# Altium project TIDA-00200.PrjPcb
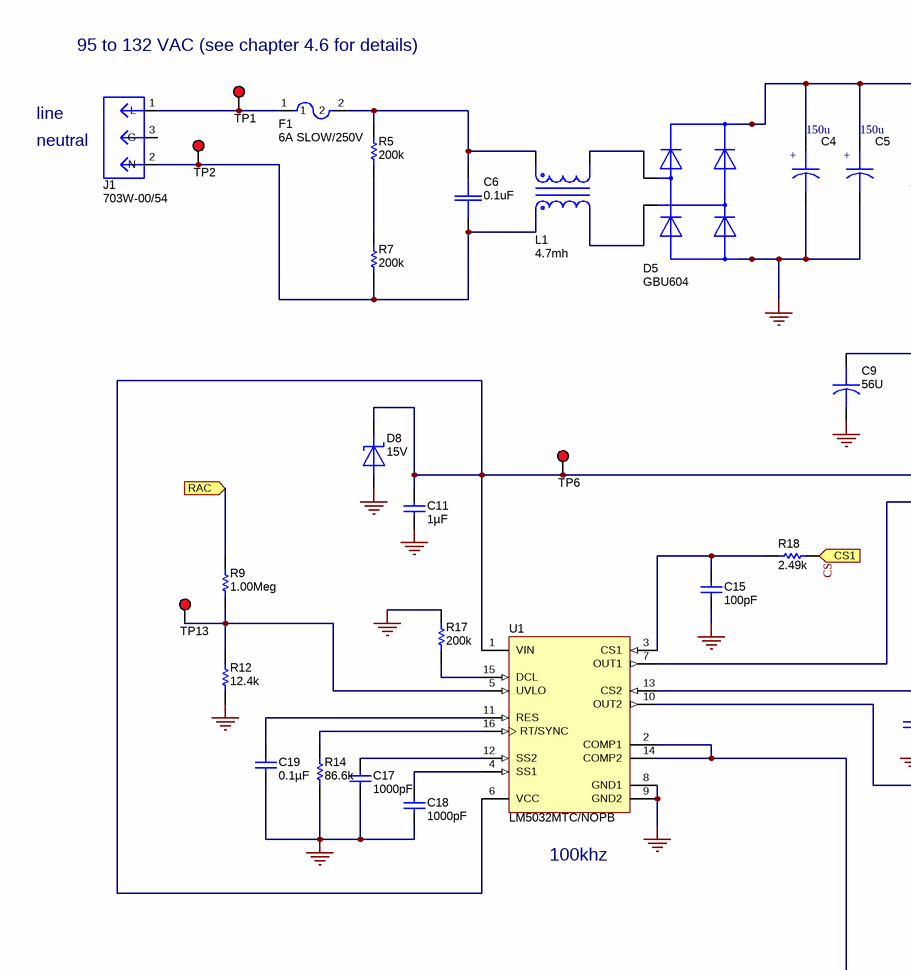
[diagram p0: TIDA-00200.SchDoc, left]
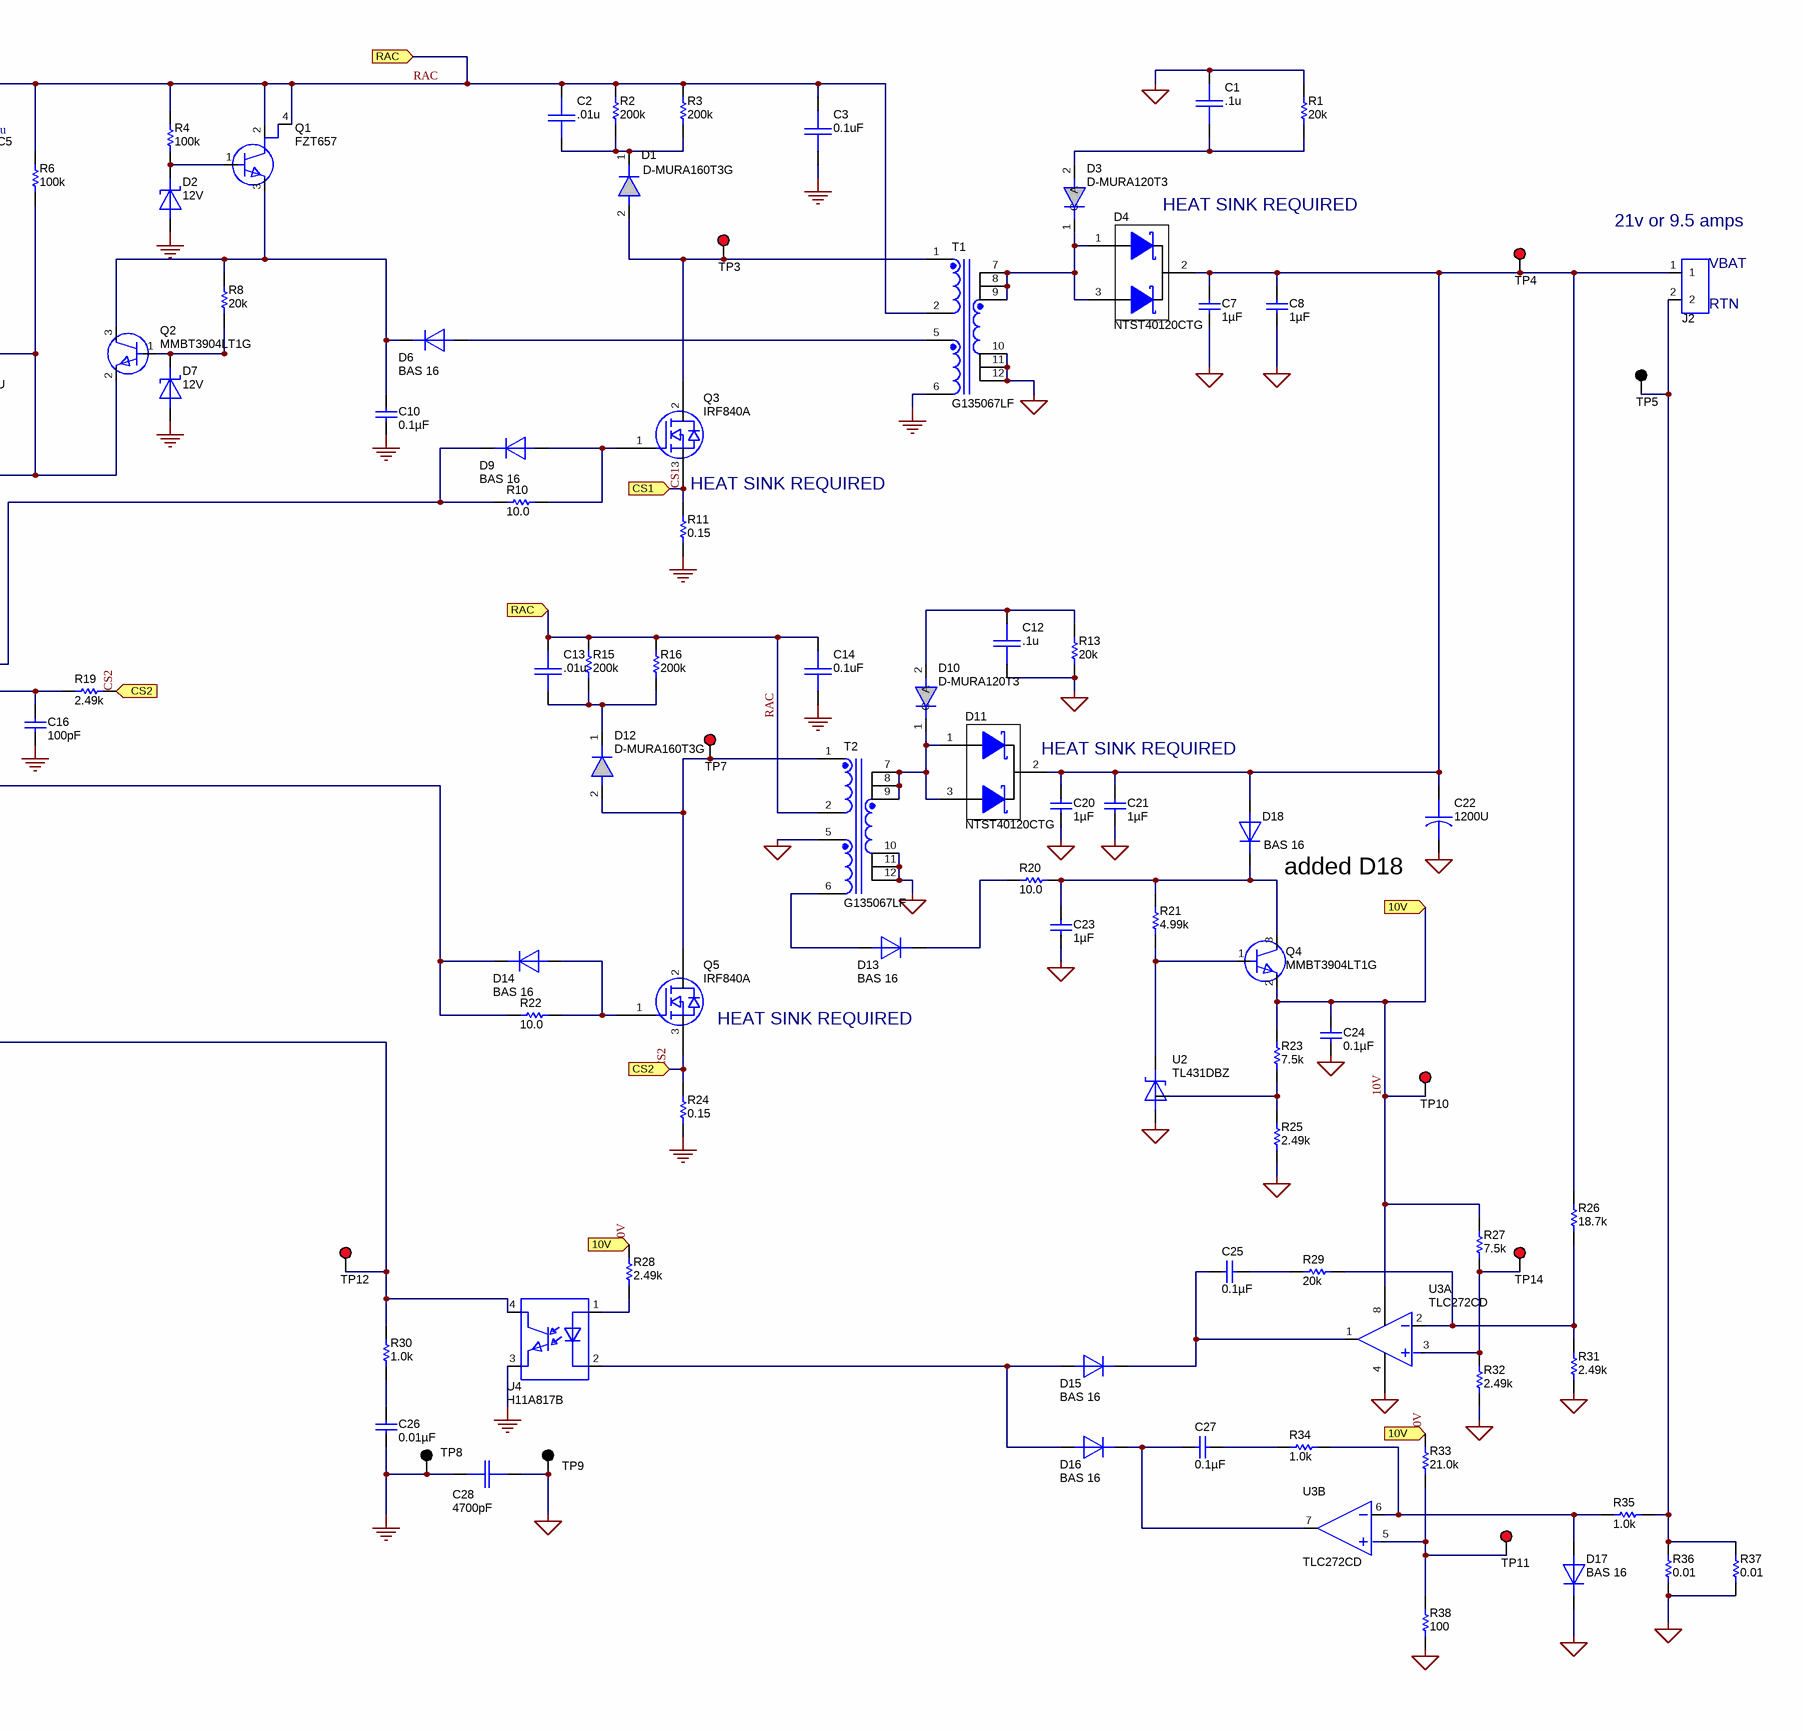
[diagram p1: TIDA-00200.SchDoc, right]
TechSupport: http://www.ti.com/support; SCH_Rev: E1; PRJ_Title: TIDA-00200; PRJ_Number: TIDA-00200; PRJ_Customer: Public Release; PCB_Rev: E1; PCB_Layout: TIDA-00200; CopyrightYear: 2014
1 sheet, 113 parts. Net scope: flat (ports and power ports of the same name join across sheets).
Board file: TIDA-00200.PcbDoc

## Sheet TIDA-00200.SchDoc
size 558 x 431 mm; Date: Not shown in title block; ApprovedBy: Not shown in title block; CheckedBy: Not shown in title block; Author: Not shown in title block; CompanyName: Not shown in title block; Engineer: Not shown in title block; Organization: Not shown in title block; Address1: Not shown in title block; Address2: Not shown in title block; Address3: Not shown in title block; Address4: Not shown in title block; DocumentNumber: 1; Revision: Use project parameter SCH_Rev; SheetNumber: 1; SheetTotal: 1; PageSetup: Record=PageOptions|CenterHorizontal=True|CenterVertical=True|PrintScale=1.00|XCorrection=1.00|YCorrection=1.00|PrintKind=0|BorderSize=5000000|LeftOffset=0|BottomOffset=0|Orientation=2|PaperLength=1000|PaperWidth=1000|Scale=100|PaperSource=15|PrintQuality=600|MediaType=1|DitherType=10|PaperKind=Letter|PrintScaleMode=1

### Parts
C1  value .1u  [C1206]  (hidden comment: C1206)
C2  value .01u  [C1206]  (hidden comment: C1206)
C3  value 0.1uF  [CAP_ECQ-E2104KB]  (hidden comment: CAP_ECQ-E2104KB)
C4  value 150u  [CAP_ZL-7.5X14.5MM]  (hidden comment: EEUEB2D151)
C5  value 150u  [CAP_ZL-7.5X14.5MM]  (hidden comment: EEUEB2D151)
C6  value 0.1uF  [CAP_590PITCH]  (hidden comment: CAP_B81130-C1104-MXXX)
C7  ValueDisplayed: 1µF  [1206]  (hidden comment: C1206C105K3RACTU)
C8  ValueDisplayed: 1µF  [1206]  (hidden comment: C1206C105K3RACTU)
C9  value 56U  [CAP_ZL-5MM]  (hidden comment: CAP_ZL_5MM_SERIES)
C10  ValueDisplayed: 0.1µF  [0603]  (hidden comment: C0603C104K5RACTU)
C11  ValueDisplayed: 1µF  [0805_HV]  (hidden comment: C0805C105K4RACTU)
C12  value .1u  [C1206]  (hidden comment: C1206)
C13  value .01u  [C1206]  (hidden comment: C1206)
C14  value 0.1uF  [CAP_ECQ-E2104KB]  (hidden comment: CAP_ECQ-E2104KB)
C15  ValueDisplayed: 100pF  [0603]  (hidden comment: C0603C101J5GACTU)
C16  ValueDisplayed: 100pF  [0603]  (hidden comment: C0603C101J5GACTU)
C17  ValueDisplayed: 1000pF  [0603]  (hidden comment: C0603C102K5RACTU)
C18  ValueDisplayed: 1000pF  [0603]  (hidden comment: C0603C102K5RACTU)
C19  ValueDisplayed: 0.1µF  [0603]  (hidden comment: C0603C104K5RACTU)
C20  ValueDisplayed: 1µF  [1206]  (hidden comment: C1206C105K3RACTU)
C21  ValueDisplayed: 1µF  [1206]  (hidden comment: C1206C105K3RACTU)
C22  value 1200U  [CAP_ZL-5X12.5MM]  (hidden comment: CAP_ZL_12.5MM_SERIES)
C23  ValueDisplayed: 1µF  [0805]  (hidden comment: C2012X7R1E105K)
C24  ValueDisplayed: 0.1µF  [0805]  (hidden comment: C0805C104K3RACTU)
C25  ValueDisplayed: 0.1µF  [0603]  (hidden comment: C0603C104K5RACTU)
C26  ValueDisplayed: 0.01µF  [0603]  (hidden comment: C0603C103K5RACTU)
C27  ValueDisplayed: 0.1µF  [0603]  (hidden comment: C0603C104K5RACTU)
C28  value 4700pF  [CAP-200MIL]  (hidden comment: CAP_ECKNVS-9MMDIA)
D1  D-MURA160T3G  [403D]
D2  value 12V  [SOT-23]  (hidden comment: D-MMBZ52XXBLT1_SERIES)
D3  D-MURA120T3  [403A]
D4  NTST40120CTG  [TO-262]
D5  value GBU604  [BRIDGE-INLINE-210-C]  (hidden comment: D-BRIDGE_GBU_SERIES)
D6  value BAS 16  [SOT-23]  (hidden comment: D-BAS16)
D7  value 12V  [SOT-23]  (hidden comment: D-MMBZ52XXBLT1_SERIES)
D8  value 15V  [SOT-23]  (hidden comment: D-MMBZ52XXBLT1_SERIES)
D9  value BAS 16  [SOT-23]  (hidden comment: D-BAS16)
D10  D-MURA120T3  [403A]
D11  NTST40120CTG  [TO-262]
D12  D-MURA160T3G  [403D]
D13  value BAS 16  [SOT-23]  (hidden comment: D-BAS16)
D14  value BAS 16  [SOT-23]  (hidden comment: D-BAS16)
D15  value BAS 16  [SOT-23]  (hidden comment: D-BAS16)
D16  value BAS 16  [SOT-23]  (hidden comment: D-BAS16)
D17  value BAS 16  [SOT-23]  (hidden comment: D-BAS16)
D18  value BAS 16  [SOT-23]  (hidden comment: D-BAS16)
F1  value 6A SLOW/250V  [FUSE_370_]  (hidden comment: FUSE_TR5_SERIES)
J1  value 703W-00/54  [CONN_AC_HP-TYPE]  (hidden comment: CONN_AC_HP-TYPE)
J2  TBLK_6A_2X3.5MM  [TB_2X3.5MM]  (value not drawn)
L1  value 4.7mh  [IND_COUPLED_1400_X_820]  (hidden comment: IND_GVTM1_SERIES)
Q1  value FZT657  [S0T223]  (hidden comment: TR-FZT649)
Q2  value MMBT3904LT1G  [SOT-23]  (hidden comment: TR-MMBT3904LT1G)
Q3  value IRF840A  [TO-220V]  (hidden comment: TR_NFET_TO-220V)
Q4  value MMBT3904LT1G  [SOT-23]  (hidden comment: TR-MMBT3904LT1G)
Q5  value IRF840A  [TO-220V]  (hidden comment: TR_NFET_TO-220V)
R1  value 20k  [1206]  (hidden comment: CRCW120620K0JNEA)
R2  value 200k  [1206]  (hidden comment: CRCW1206200KJNEA)
R3  value 200k  [1206]  (hidden comment: CRCW1206200KJNEA)
R4  value 100k  [1206]  (hidden comment: CRCW1206100KJNEA)
R5  value 200k  [1206]  (hidden comment: CRCW1206200KJNEA)
R6  value 100k  [1206]  (hidden comment: CRCW1206100KJNEA)
R7  value 200k  [1206]  (hidden comment: CRCW1206200KJNEA)
R8  value 20k  [0603]  (hidden comment: CRCW060320K0JNEA)
R9  value 1.00Meg  [1206]  (hidden comment: CRCW12061M00FKEA)
R10  value 10.0  [0603]  (hidden comment: CRCW060310R0FKEA)
R11  value 0.15  [1206]  (hidden comment: ERJ-8RSJR15V)
R12  value 12.4k  [0603]  (hidden comment: CRCW060312K4FKEA)
R13  value 20k  [1206]  (hidden comment: CRCW120620K0JNEA)
R14  value 86.6k  [0603]  (hidden comment: CRCW060386K6FKEA)
R15  value 200k  [1206]  (hidden comment: CRCW1206200KJNEA)
R16  value 200k  [1206]  (hidden comment: CRCW1206200KJNEA)
R17  value 200k  [0603]  (hidden comment: CRCW0603200KJNEA)
R18  value 2.49k  [0603]  (hidden comment: CRCW06032K49FKEA)
R19  value 2.49k  [0603]  (hidden comment: CRCW06032K49FKEA)
R20  value 10.0  [0603]  (hidden comment: CRCW060310R0FKEA)
R21  value 4.99k  [0603]  (hidden comment: CRCW06034K99FKEA)
R22  value 10.0  [0603]  (hidden comment: CRCW060310R0FKEA)
R23  value 7.5k  [0603]  (hidden comment: CRCW06037K50JNEA)
R24  value 0.15  [1206]  (hidden comment: ERJ-8RSJR15V)
R25  value 2.49k  [0603]  (hidden comment: CRCW06032K49FKEA)
R26  value 18.7k  [0603]  (hidden comment: CRCW060318K7FKEA)
R27  value 7.5k  [0603]  (hidden comment: CRCW06037K50JNEA)
R28  value 2.49k  [0603S]  (hidden comment: CRCW06032K49FKEA)
R29  value 20k  [0603]  (hidden comment: CRCW060320K0JNEA)
R30  value 1.0k  [0603]  (hidden comment: CRCW06031K00JNEA)
R31  value 2.49k  [0603]  (hidden comment: CRCW06032K49FKEA)
R32  value 2.49k  [0603]  (hidden comment: CRCW06032K49FKEA)
R33  value 21.0k  [0603]  (hidden comment: CRCW060321K0FKEA)
R34  value 1.0k  [0603]  (hidden comment: CRCW06031K00JNEA)
R35  value 1.0k  [0603]  (hidden comment: CRCW06031K00JNEA)
R36  value 0.01  [2512M]  (hidden comment: WSL2512R0100FEA)
R37  value 0.01  [2512M]  (hidden comment: WSL2512R0100FEA)
R38  value 100  [0603]  (hidden comment: CRCW0603100RJNEA)
T1  G135067LF  [GCI_G135067LF-rev3]
T2  G135067LF  [GCI_G135067LF-rev3]
TP1  5000  [Keystone5000]  (value not drawn)
TP2  5000  [Keystone5000]  (value not drawn)
TP3  5000  [Keystone5000]  (value not drawn)
TP4  5000  [Keystone5000]  (value not drawn)
TP5  5001  [Keystone5001]  (value not drawn)
TP6  5000  [Keystone5000]  (value not drawn)
TP7  5000  [Keystone5000]  (value not drawn)
TP8  5001  [Keystone5001]  (value not drawn)
TP9  5001  [Keystone5001]  (value not drawn)
TP10  5000  [Keystone5000]  (value not drawn)
TP11  5000  [Keystone5000]  (value not drawn)
TP12  5000  [Keystone5000]  (value not drawn)
TP13  5000  [Keystone5000]  (value not drawn)
TP14  5000  [Keystone5000]  (value not drawn)
U1  LM5032MTC/NOPB  [MTC16_N]
U2  value TL431DBZ  [SOT-23]  (hidden comment: TL431AIDBZ)
U3  TLC272CD  [SO8]  (parts A,B of 2)
U4  value H11A817B  [H11_OPTO_4P]  (hidden comment: _H11A817)

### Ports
10V, CS1, CS2, RAC

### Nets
Pgnd: C3.1 C4.2 C5.2 C9.2 C10.1 C11.1 C14.1 C15.1 C16.1 C17.1 C18.1 C19.1 C26.1 C28.1 D2.1(A) D5.4(-) D7.1(A) D8.1(A) R11.2 R12.1 R14.1 R17.1 R24.2 T1.6 TP8.1 U1.8(GND1) U1.9(GND2) U4.3(E)
Sgnd: C1.1 C7.1 C8.1 C12.2 C20.1 C21.1 C22.2 C23.1 C24.1 C28.2 D17.3(A) R1.2 R13.1 R25.2 R31.2 R32.2 R36.2 R37.2 R38.2 T1.10 T1.11 T1.12 T2.5 T2.10 T2.11 T2.12 TP9.1 U2.3(A) U3.4(GND)
10V: C24.2 Q4.2(E) R23.1 R27.1 R28.1 R33.1 TP10.1 U3.8(VCC) ; port 10V
CS1: Q3.3(S) R11.1 R18.1 ; port CS1
CS2: Q5.3(S) R19.1 R24.1 ; port CS2
RAC: C2.2 C3.2 C4.1 C5.1 C13.2 C14.2 D5.1(+) Q1.2(C) Q1.4(C) R2.1 R3.1 R4.1 R6.1 R9.1 R15.1 R16.1 T1.2 T2.2 ; port RAC
NetC1_2: C1.2 D3.2(A) R1.1
NetC2_1: C2.1 D1.1 R2.2 R3.2
NetC6_1: C6.1 J1.2(N) L1.1 R7.2 TP2.1
NetC6_2: C6.2 F1.2 L1.2 R5.1
NetC7_2: C7.2 C8.2 C20.2 C21.2 C22.1 D4.2(K) D11.2(K) D18.1(C) J2.1 R26.1 TP4.1
NetC9_1: C9.1 C11.2 D8.3(C) Q2.2(E) R6.2 TP6.1 U1.1(VIN) U1.6(VCC)
NetC10_2: C10.2 D6.3(A) Q1.3(E) Q2.3(C) R8.2
NetC12_1: C12.1 D10.2(A) R13.2
NetC13_1: C13.1 D12.1 R15.2 R16.2
NetC15_2: C15.2 R18.2 U1.3(CS1)
NetC16_2: C16.2 R19.2 U1.13(CS2)
NetC17_2: C17.2 U1.12(SS2)
NetC18_2: C18.2 U1.4(SS1)
NetC19_2: C19.2 U1.11(RES)
NetC23_2: C23.2 D18.3(A) Q4.3(C) R20.2 R21.1
NetC25_1: C25.1 R29.1
NetC25_2: C25.2 D15.3(A) U3.1(OUT1)
NetC26_2: C26.2 R30.1
NetC27_1: C27.1 R34.1
NetC27_2: C27.2 D16.3(A) U3.7(OUT)
NetD1_2: D1.2 Q3.2(D) T1.1 TP3.1
NetD2_3: D2.3(C) Q1.1(B) R4.2
NetD3_1: D3.1(C) D4.1(A) D4.3(A) T1.7 T1.8 T1.9
NetD5_2: D5.2(AC) L1.3
NetD5_3: D5.3(AC) L1.4
NetD6_1: D6.1(C) T1.5
NetD7_3: D7.3(C) Q2.1(B) R8.1
NetD9_1: D9.1(C) Q3.1(G) R10.2
NetD9_3: D9.3(A) R10.1 U1.7(OUT1)
NetD10_1: D10.1(C) D11.1(A) D11.3(A) T2.7 T2.8 T2.9
NetD12_2: D12.2 Q5.2(D) T2.1 TP7.1
NetD13_1: D13.1(C) T2.6
NetD13_3: D13.3(A) R20.1
NetD14_1: D14.1(C) Q5.1(G) R22.2
NetD14_3: D14.3(A) R22.1 U1.10(OUT2)
NetD15_1: D15.1(C) D16.1(C) U4.2(K)
NetD17_1: D17.1(C) R34.2 R35.1 U3.6(IN-)
NetF1_1: F1.1 J1.1(L) TP1.1
NetJ2_2: J2.2 R35.2 R36.1 R37.1 TP5.1
NetQ4_1: Q4.1(B) R21.2 U2.1(C)
NetR5_2: R5.2 R7.1
NetR9_2: R9.2 R12.2 TP13.1 U1.5(UVLO)
NetR14_2: R14.2 U1.16(RT/SYNC)
NetR17_2: R17.2 U1.15(DCL)
NetR23_2: R23.2 R25.1 U2.2(REF)
NetR26_2: R26.2 R29.2 R31.1 U3.2(IN-)
NetR27_2: R27.2 R32.1 TP14.1 U3.3(IN+)
NetR28_2: R28.2 U4.1(A)
NetR30_2: R30.2 TP12.1 U1.2(COMP1) U1.14(COMP2) U4.4(C)
NetR33_2: R33.2 R38.1 TP11.1 U3.5(IN+)

Not connected (* = marked no-connect by the designer): J1 3(G)

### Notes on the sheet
- 95 to 132 VAC (see chapter 4.6 for details)
- line
- (near J1) neutral
- (near D4) HEAT SINK REQUIRED
- (near J2) 21v or 9.5 amps
- (near J2) VBAT
- (near J2) RTN
- HEAT SINK REQUIRED
- (near D11) HEAT SINK REQUIRED
- (near U1) 100khz
- added D18
- (near Q5) HEAT SINK REQUIRED

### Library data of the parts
C1 C12 = C1206: Capacitor, Ceramic, 250V, [temp],  [tol]; Manufacturer: muRata; PartNumber: GRM42-6yyyxxxKvv; Area: 15390
C2 C13 = C1206: Capacitor, Ceramic Chip, 250V, ±10%; Manufacturer: STD; Area: 15390
C3 C14 = CAP_ECQ-E2104KB: Capacitor, Polyester, 400V, 10%; Manufacturer: Panasonic; Area: 82863
C4 C5 = CAP_ZL_16MM_SERIES: Capacitor, multi pattern, TH 0.080 to 0.200; Manufacturer: panasonic; Area: 283,687
C6 = CAP_B81130-C1104-MXXX: Capacitor, Leaded, 0.10 uF, 275 VAC, X2; Mfr_: EPCOS; Area: 198,640; Volts: 275VAC
C7 C8 C20 C21 = C1206C105K3RACTU: CAP, CERM, 1uF, 25V, +/-10%, X7R, 1206; Manufacturer: Kemet; Polarized: N; CompType: Capacitor; U/M: EA; Cap_F: 0.000001; Tolerance_%: 10; ESR_Ohm: 0.011; Value1: 0.011 ohm; VDC_V: 25; IRMS_A: 3.55; TaMin_C: -55; TaMax_C: 125
C9 = CAP_ZL_5MM_SERIES: Capacitor, Aluminum Electrolytic, vvV; PartNumber: 16ZL56 5X11; Manufacturer: Rubycon; Second Source: C:\program files\p-cad 2004\pcad_pdf's\e_ZL.pdf; Area: 40,471
C10 C19 C25 C27 = C0603C104K5RACTU: CAP, CERM, 0.1uF, 50V, +/-10%, X7R, 0603; Manufacturer: Kemet; Polarized: N; CompType: Capacitor; U/M: EA; Cap_F: 0.0000001; Tolerance_%: 10; Value1: Unknown; VDC_V: 50; TaMin_C: -55; TaMax_C: 125
C11 = C0805C105K4RACTU: CAP, CERM, 1uF, 16V, +/-10%, X7R, 0805; Manufacturer: Kemet; Polarized: N; CompType: Capacitor; U/M: EA; Cap_F: 0.000001; Tolerance_%: 10; ESR_Ohm: 0.015; Value1: 0.015 ohm; VDC_V: 16; IRMS_A: 8.19; TaMin_C: -55; TaMax_C: 125; Cap_Case: 0805
C15 C16 = C0603C101J5GACTU: CAP, CERM, 100pF, 50V, +/-5%, C0G/NP0, 0603; Manufacturer: Kemet; Polarized: N; CompType: Capacitor; U/M: EA; Cap_F: 0.0000000001; Tolerance_%: 5; Value1: Unknown; VDC_V: 50; TaMin_C: -55; TaMax_C: 125
C17 C18 = C0603C102K5RACTU: CAP, CERM, 1000pF, 50V, +/-10%, X7R, 0603; Manufacturer: Kemet; Polarized: N; CompType: Capacitor; U/M: EA; Cap_F: 0.000000001; Tolerance_%: 10; Value1: Unknown; VDC_V: 50; TaMin_C: -55; TaMax_C: 125
C22 = CAP_ZL_12.5MM_SERIES: Capacitor, multi pattern, SM 1210 to E case + F THole; PartNumber: 35ZL1200 12.5X20; Manufacturer: Rubycon; Second Source: C:\program files\p-cad 2004\pcad_pdf's\e_ZL.pdf; Area: 214,008
C23 = C2012X7R1E105K: CAP, CERM, 1uF, 25V, +/-10%, X7R, 0805; Manufacturer: TDK; Polarized: N; CompType: Capacitor; U/M: EA; Cap_F: 0.000001; Tolerance_%: 10; ESR_Ohm: 0.0075; Value1: 0.0075 ohm; VDC_V: 25; TaMin_C: -55; TaMax_C: 125
C24 = C0805C104K3RACTU: CAP, CERM, 0.1uF, 25V, +/-10%, X7R, 0805; Manufacturer: Kemet; Polarized: N; CompType: Capacitor; U/M: EA; Cap_F: 0.0000001; Tolerance_%: 10; ESR_Ohm: 0.064; Value1: 0.064 ohm; VDC_V: 25; IRMS_A: 1.64; TaMin_C: -55; TaMax_C: 125
C26 = C0603C103K5RACTU: CAP, CERM, 0.01uF, 50V, +/-10%, X7R, 0603; Manufacturer: Kemet; Polarized: N; CompType: Capacitor; U/M: EA; Cap_F: 0.00000001; Tolerance_%: 10; Value1: Unknown; VDC_V: 50; TaMin_C: -55; TaMax_C: 125
C28 = CAP_ECKNVS-9MMDIA: Capacitor, Ceramic Disc, 250WV, 4700pF, Y5U ±20%; PartNumber: DE2EKY472MA2BM01; Manufacturer: Panasonic; Area: 102,600; Voltage: 250VAC
D1 D12 = D-MURA160T3G: Rectifier, SMD Ultrafast  Power, 600V 1A; Manufacturer: On Semi; Area: 4088
D2 D7 = D-MMBZ52XXBLT1_SERIES: Diode, Zener, 12V, yy-mA; Manufacturer: Diodes; PartNumber: MMBZ5242BLT1; Area: 195000; Type: D_ZENER_SOT23; Second Source: C:\program files\p-cad 2004\pcad_pdf's\MMBZ5221BLT1-D[1].pdf
D3 D10 = D-MURA120T3: Diode, UltraFast Rectifier, 1-A, 200-V; Manufacturer: On Semi; Area: 64000
D4 D11 = VS-48CTQ060-1PbF: Diode, Schottky, 60V, 20A, TH; Manufacturer: Vishay-Semiconductor; SymbolCreator: a0411947; Value: 100V; U/M: EA; Vf_V: 0.58; Value2: 0.58V; Io_A: 20; TJmax_C: 150; RJC_CperW: 2
D5 = D-BRIDGE_GBU_SERIES: Diode, Bridge Rectifier, 6 A, 400V; Manufacturer: Fairchild; Area: 163800; Second_Source: C:\program files\p-cad 2004\pcad_pdf's\GBU8A_M.pdf; Type: D-BRIDGE_GBU SERIES
D6 D9 D13-D18 = D-BAS16: Diode, Switching, 200mA, 100V, 300mW; Manufacturer: Vishay-Liteon; PartNumber: BAS16; Area: 14105; NC: 2; Second Source: C:\program files\p-cad 2004\pcad_pdf's\bas16v.pdf
D8 = D-MMBZ52XXBLT1_SERIES: Diode, Zener, 15V, yy-mA; Manufacturer: Diodes; PartNumber: MMBZ5245BLT1; Area: 195000; Type: D_ZENER_SOT23; Second Source: C:\program files\p-cad 2004\pcad_pdf's\MMBZ5221BLT1-D[1].pdf
F1 = FUSE_TR5_SERIES: Fuse, TR5 Series, 6 slow, 250V; Manufacturer: Wickmann; PartNumber: 370 1400 041; Area: 104,635; Type: FUSE TR5 SERIES
J1 = CONN_AC_HP-TYPE: Connector, AC Board mount, 9mm; Manufacturer: Qualtek Electronics; Area: 1.64 inch; NC: MT1,MT2; Second Source: \\vette02\pmp_pcb\pcad_pdf's\
J2 = TBLK_6A_2X3.5MM: Terminal Block, 2-pin, 6-A, 3.5mm; Manufacturer: OST; PartNumber: ED555/2DS; Second Source: C:\program files\p-cad 2004\pcad_pdf's\ED555DS.pdf; area: 70125; Value: ED555/2DS
L1 = IND_GVTM1_SERIES: Inductor, Common Mode Choke,; Manufacturer: GCI; PartNumber: GVTM1-472; Area: 891,1
Q1 = TR-FZT649: Trans, NPN Midium Power, 300V 3A; Manufacturer: Zetex; Area: 98600
Q2 Q4 = TR-MMBT3904LT1G: Trans, NPN, xx-V, yy-mA, zz-W; Manufacturer: On Semi; Second Source: C:\program files\p-cad 2004\pcad_pdf's\MMBT3904LT1-D.pdf; Area: 14105
Q3 Q5 = TR_NFET_TO-220V: MOSFET, N-ch, 500-V, yy-A, 85-milliOhms; PartNumber: STD; Area: 110700
R1 R13 = CRCW120620K0JNEA: RES, 20k ohm, 5%, 0.25W, 1206; Manufacturer: Vishay-Dale; CompType: Resistor; Res_ohm: 20000; Value_Code: 20k0; Tolerance_%: 5; Power_W: 0.25; VDC_V: 200; TempCo: 200 ppm/C; EIA_Code: E24; U/M: EA
R2 R3 R5 R7 R15 R16 = CRCW1206200KJNEA: RES, 200k ohm, 5%, 0.25W, 1206; Manufacturer: Vishay-Dale; CompType: Resistor; Res_ohm: 200000; Tolerance_%: 5; Power_W: 0.25; VDC_V: 200; TempCo: 200 ppm/C; EIA_Code: E24; U/M: EA
R4 R6 = CRCW1206100KJNEA: RES, 100k ohm, 5%, 0.25W, 1206; Manufacturer: Vishay-Dale; CompType: Resistor; Res_ohm: 100000; Tolerance_%: 5; Power_W: 0.25; VDC_V: 200; TempCo: 200 ppm/C; EIA_Code: E24; U/M: EA
R8 R29 = CRCW060320K0JNEA: RES, 20k ohm, 5%, 0.1W, 0603; Manufacturer: Vishay-Dale; CompType: Resistor; Res_ohm: 20000; Value_Code: 20k0; Tolerance_%: 5; Power_W: 0.1; VDC_V: 75; TempCo: 200 ppm/C; EIA_Code: E24; U/M: EA
R9 = CRCW12061M00FKEA: RES, 1.00Meg ohm, 1%, 0.25W, 1206; Manufacturer: Vishay-Dale; CompType: Resistor; Res_ohm: 1000000; Value_Code: 1M00; Tolerance_%: 1; Power_W: 0.25; VDC_V: 200; TempCo: 100 ppm/C; EIA_Code: E96; U/M: EA
R10 R20 R22 = CRCW060310R0FKEA: RES, 10.0 ohm, 1%, 0.1W, 0603; Manufacturer: Vishay-Dale; CompType: Resistor; Res_ohm: 10; Value_Code: 10R0; Tolerance_%: 1; Power_W: 0.1; VDC_V: 75; TempCo: 100 ppm/C; EIA_Code: E96; U/M: EA
R11 R24 = ERJ-8RSJR15V: RES, 0.15 ohm, 5%, 0.25W, 1206; Manufacturer: Panasonic; CompType: Resistor; Value_Code: R150; Tolerance_%: 5; Power_W: 0.25; TempCo: 250 ppm/C; EIA_Code: E24; U/M: EA
R12 = CRCW060312K4FKEA: RES, 12.4k ohm, 1%, 0.1W, 0603; Manufacturer: Vishay-Dale; CompType: Resistor; Res_ohm: 12400; Value_Code: 12k4; Tolerance_%: 1; Power_W: 0.1; VDC_V: 75; TempCo: 100 ppm/C; EIA_Code: E96; U/M: EA
R14 = CRCW060386K6FKEA: RES, 86.6k ohm, 1%, 0.1W, 0603; Manufacturer: Vishay-Dale; CompType: Resistor; Res_ohm: 86600; Value_Code: 86k6; Tolerance_%: 1; Power_W: 0.1; VDC_V: 75; TempCo: 100 ppm/C; EIA_Code: E96; U/M: EA
R17 = CRCW0603200KJNEA: RES, 200k ohm, 5%, 0.1W, 0603; Manufacturer: Vishay-Dale; CompType: Resistor; Res_ohm: 200000; Tolerance_%: 5; Power_W: 0.1; VDC_V: 75; TempCo: 200 ppm/C; EIA_Code: E24; U/M: EA
R18 R19 R25 R28 R31 R32 = CRCW06032K49FKEA: RES, 2.49k ohm, 1%, 0.1W, 0603; Manufacturer: Vishay-Dale; CompType: Resistor; Res_ohm: 2490; Value_Code: 2k49; Tolerance_%: 1; Power_W: 0.1; VDC_V: 75; TempCo: 100 ppm/C; EIA_Code: E96; U/M: EA
R21 = CRCW06034K99FKEA: RES, 4.99k ohm, 1%, 0.1W, 0603; Manufacturer: Vishay-Dale; CompType: Resistor; Res_ohm: 4990; Value_Code: 4k99; Tolerance_%: 1; Power_W: 0.1; VDC_V: 75; TempCo: 100 ppm/C; EIA_Code: E96; U/M: EA
R23 R27 = CRCW06037K50JNEA: RES, 7.5k ohm, 5%, 0.1W, 0603; Manufacturer: Vishay-Dale; CompType: Resistor; Res_ohm: 7500; Value_Code: 7k50; Tolerance_%: 5; Power_W: 0.1; VDC_V: 75; TempCo: 200 ppm/C; EIA_Code: E24; U/M: EA
R26 = CRCW060318K7FKEA: RES, 18.7k ohm, 1%, 0.1W, 0603; Manufacturer: Vishay-Dale; CompType: Resistor; Res_ohm: 18700; Value_Code: 18k7; Tolerance_%: 1; Power_W: 0.1; VDC_V: 75; TempCo: 100 ppm/C; EIA_Code: E96; U/M: EA
R30 R34 R35 = CRCW06031K00JNEA: RES, 1.0k ohm, 5%, 0.1W, 0603; Manufacturer: Vishay-Dale; CompType: Resistor; Res_ohm: 1000; Value_Code: 1k00; Tolerance_%: 5; Power_W: 0.1; VDC_V: 75; TempCo: 200 ppm/C; EIA_Code: E24; U/M: EA
R33 = CRCW060321K0FKEA: RES, 21.0k ohm, 1%, 0.1W, 0603; Manufacturer: Vishay-Dale; CompType: Resistor; Res_ohm: 21000; Value_Code: 21k0; Tolerance_%: 1; Power_W: 0.1; VDC_V: 75; TempCo: 100 ppm/C; EIA_Code: E96; U/M: EA
R36 R37 = WSL2512R0100FEA: RES, 0.01 ohm, 1%, 1W, 2512; Manufacturer: Vishay-Dale; CompType: Resistor; Value_Code: R010; Tolerance_%: 1; TempCo: 75 ppm/C; EIA_Code: E96; U/M: EA
R38 = CRCW0603100RJNEA: RES, 100 ohm, 5%, 0.1W, 0603; Manufacturer: Vishay-Dale; CompType: Resistor; Value_Code: 100R; Tolerance_%: 5; Power_W: 0.1; VDC_V: 75; TempCo: 200 ppm/C; EIA_Code: E24; U/M: EA
T1 T2 = G135067LF: Transformer, Flyback, 500uH, TH; Manufacturer: GCI Technologies; SymbolCreator: a0799628; DCR_Ohm: 0.26; LeakageL: 5uH; U/M: EA
TP1-TP4 TP6 TP7 TP10-TP14 = 5000: Test Point, Miniature, Red, TH; Manufacturer: Keystone; CompType: Test Point Loop; U/M: EA
TP5 TP8 TP9 = 5001: Test Point, Miniature, Black, TH; Manufacturer: Keystone; CompType: Test Point Loop; U/M: EA
U1 = LM5032MTC/NOPB: High Voltage Dual Interleaved Current Mode Controller, 16-pin TSSOP, Pb-Free; Manufacturer: National Semiconductor; PackageTopMarking: NSUZXYTT*LM5032*MTC; PowerWise: Y; CompType: MiscPower
U2 = TL431AIDBZ: IC, Precision Adjustable Shunt Regulator; Manufacturer: TI; PartNumber: TL431DBVZ; Alternate Manufacturer: None; Area: 16384; Second Source: C:\program files\p-cad 2004\pcad_pdf's\TL431A-B.pdf
U3 = TLC272CD: IC, Precision Dual Operational Amplifiers; Manufacturer: TI; Alternate Manufacturer: None; Second Source: C:\program files\p-cad 2004\pcad_pdf's\tlc272.pdf; Area: 75900
U4 = _H11A817: IC, Optocoupler, 5300-V, 80-160% CTR; Manufacturer: QT Optoelectronics; Area: 74100

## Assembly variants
001: all parts fitted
